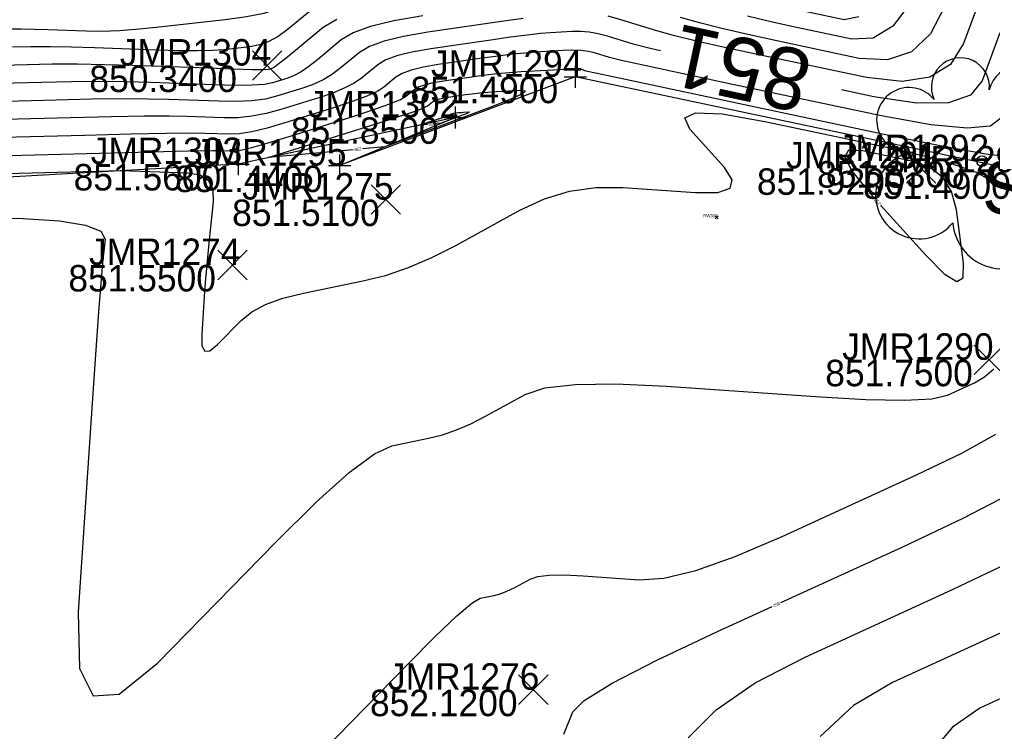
# Model space of a CAD drawing. Extents: x 1654928 to 1810050, y 486881 to 626330.
# Drawn here: x 1801514.13 to 1801558.26, y 489797.37 to 489829.65 of the extents above; entities that cross this region are included whole.
import ezdxf

# ---------------------------------------------------------------- set-up
doc = ezdxf.new("R2010")
doc.units = 0
for name, color, linetype in [('DT_X_Contour_Major', 7, 'Continuous'), ('DT_X_Contour_Minor', 7, 'Continuous'), ('GK_Visualization', 7, 'Continuous'), ('SV_X_Random_Point', 7, 'Continuous'), ('SV_X_Shot_Marker', 7, 'Continuous'), ('SV_X_Text_Elevation', 7, 'Continuous'), ('SV_X_Text_Name', 7, 'Continuous'), ('SV_X_Top_of_Bank', 7, 'Continuous'), ('VG_X_Cells', 7, 'Continuous'), ('VG_X_Text', 7, 'Continuous')]:
    doc.layers.add(name, color=color, linetype=linetype)

msp = doc.modelspace()

# ---------------------------------------------------------------- linework, layer by layer
at = {"layer": 'DT_X_Contour_Major'}
for points in [[(1801526.541, 489830.649), (1801526.157, 489830.333), (1801525.78, 489830.118), (1801525.204, 489829.93), (1801524.429, 489829.769), (1801523.455, 489829.635), (1801520.593, 489829.314), (1801519.572, 489829.211), (1801518.658, 489829.145), (1801517.85, 489829.115), (1801517.148, 489829.12), (1801515.416, 489829.184), (1801514.789, 489829.203), (1801514.203, 489829.213), (1801513.661, 489829.214)], [(1801543.196, 489828.229), (1801542.61, 489828.367), (1801541.961, 489828.539), (1801540.801, 489828.891), (1801540.375, 489829.004), (1801539.964, 489829.078), (1801539.568, 489829.114), (1801539.189, 489829.111), (1801538.198, 489829.051), (1801537.751, 489829.014), (1801537.152, 489828.947), (1801536.401, 489828.849), (1801535.497, 489828.722), (1801532.887, 489828.342), (1801531.995, 489828.188), (1801531.28, 489828.014), (1801530.74, 489827.818), (1801530.375, 489827.6), (1801529.638, 489826.993), (1801529.312, 489826.767), (1801528.89, 489826.547), (1801528.37, 489826.331), (1801527.754, 489826.12), (1801525.98, 489825.565), (1801525.319, 489825.386), (1801524.669, 489825.264), (1801524.029, 489825.2), (1801523.399, 489825.194), (1801521.733, 489825.255), (1801520.934, 489825.269), (1801519.786, 489825.264), (1801518.288, 489825.24), (1801516.442, 489825.197), (1801511.052, 489825.058)], [(1801558.591, 489829.045), (1801557.789, 489826.872), (1801557.256, 489826.216), (1801556.26, 489825.877), (1801554.802, 489825.856), (1801552.88, 489826.152), (1801551.409, 489826.463)], [(1801527.895, 489796.5), (1801531.703, 489800.397), (1801532.982, 489801.682), (1801533.962, 489802.613), (1801534.643, 489803.19), (1801535.026, 489803.415), (1801535.649, 489803.542), (1801535.884, 489803.601), (1801536.125, 489803.682), (1801536.369, 489803.787), (1801536.619, 489803.914), (1801537.29, 489804.283), (1801537.629, 489804.395), (1801538.143, 489804.457), (1801538.832, 489804.467), (1801539.695, 489804.427), (1801542.231, 489804.25), (1801543.349, 489804.323), (1801544.802, 489804.674), (1801546.589, 489805.304), (1801548.71, 489806.213), (1801554.813, 489809.007), (1801556.856, 489809.993), (1801558.409, 489810.856)]]:
    msp.add_lwpolyline(points, dxfattribs=at)
at = {"layer": 'DT_X_Contour_Minor'}
for points in [[(1801558.073, 489831.626), (1801556.942, 489828.567), (1801556.349, 489827.609), (1801555.418, 489827.033), (1801554.15, 489826.837), (1801552.543, 489827.022), (1801547.808, 489828.022), (1801546.178, 489828.373), (1801544.838, 489828.677), (1801543.79, 489828.934), (1801543.032, 489829.144), (1801541.4, 489829.64), (1801540.829, 489829.8)], [(1801527.34, 489830.066), (1801526.264, 489829.18), (1801525.856, 489828.883), (1801525.439, 489828.657), (1801525.011, 489828.501), (1801524.574, 489828.416), (1801523.395, 489828.284), (1801522.875, 489828.245), (1801522.198, 489828.229), (1801521.365, 489828.235), (1801520.375, 489828.263), (1801517.527, 489828.367), (1801516.494, 489828.399), (1801515.532, 489828.416), (1801514.64, 489828.418), (1801513.818, 489828.405)], [(1801556.096, 489830.261), (1801555.442, 489829.003), (1801554.576, 489828.188), (1801553.498, 489827.818), (1801552.206, 489827.891), (1801548.479, 489828.679), (1801547.157, 489828.967), (1801545.987, 489829.241), (1801544.969, 489829.502), (1801544.104, 489829.749)], [(1801554.536, 489830.396), (1801553.735, 489829.344), (1801552.846, 489828.799), (1801551.87, 489828.761), (1801549.15, 489829.335), (1801548.136, 489829.56), (1801547.136, 489829.805)], [(1801536.97, 489829.703), (1801535.877, 489829.547), (1801532.652, 489829.077), (1801531.551, 489828.888), (1801530.667, 489828.672), (1801530, 489828.43), (1801529.549, 489828.162), (1801528.638, 489827.411), (1801528.281, 489827.146), (1801527.894, 489826.916), (1801527.476, 489826.72), (1801527.027, 489826.557), (1801525.791, 489826.17), (1801525.279, 489826.047), (1801524.671, 489825.968), (1801523.967, 489825.933), (1801523.168, 489825.942), (1801520.906, 489826.025), (1801519.95, 489826.047), (1801518.778, 489826.049), (1801517.39, 489826.034), (1801515.786, 489825.999), (1801511.219, 489825.881)], [(1801532.417, 489829.813), (1801531.106, 489829.587), (1801530.054, 489829.33), (1801529.26, 489829.042), (1801528.724, 489828.723), (1801527.639, 489827.829), (1801527.25, 489827.525), (1801526.898, 489827.285), (1801526.581, 489827.108), (1801526.301, 489826.995), (1801525.602, 489826.776), (1801525.239, 489826.709), (1801524.673, 489826.672), (1801523.906, 489826.666), (1801522.936, 489826.69), (1801520.08, 489826.795), (1801518.967, 489826.824), (1801517.771, 489826.835), (1801516.492, 489826.828), (1801515.13, 489826.801), (1801511.386, 489826.705)], [(1801528.52, 489829.655), (1801527.898, 489829.284), (1801526.639, 489828.247), (1801526.219, 489827.905), (1801525.901, 489827.654), (1801525.687, 489827.497), (1801525.575, 489827.432), (1801525.413, 489827.381), (1801525.199, 489827.371), (1801524.676, 489827.376), (1801523.844, 489827.399), (1801522.704, 489827.438), (1801519.253, 489827.564), (1801517.983, 489827.602), (1801516.764, 489827.621), (1801515.594, 489827.622), (1801514.474, 489827.603), (1801511.553, 489827.528)], [(1801552.194, 489829.78), (1801551.533, 489829.63), (1801549.82, 489829.992)], [(1801558.635, 489825.178), (1801558.163, 489824.823), (1801557.102, 489824.722), (1801555.453, 489824.875), (1801553.216, 489825.283), (1801546.466, 489826.709), (1801544.219, 489827.186), (1801542.541, 489827.55), (1801541.431, 489827.799), (1801540.889, 489827.934), (1801540.203, 489828.143), (1801539.92, 489828.208), (1801539.587, 489828.246), (1801539.202, 489828.258), (1801538.767, 489828.244), (1801537.537, 489828.17), (1801537.04, 489828.132), (1801536.471, 489828.074), (1801535.831, 489827.996), (1801535.118, 489827.897), (1801533.121, 489827.606), (1801532.44, 489827.489), (1801531.893, 489827.355), (1801531.48, 489827.205), (1801531.201, 489827.039), (1801530.637, 489826.575), (1801530.343, 489826.388), (1801529.886, 489826.177), (1801529.265, 489825.942), (1801528.48, 489825.683), (1801526.168, 489824.96), (1801525.36, 489824.724), (1801524.667, 489824.56), (1801524.091, 489824.467), (1801523.631, 489824.446), (1801522.56, 489824.485), (1801521.917, 489824.491), (1801520.793, 489824.478), (1801519.186, 489824.446), (1801517.098, 489824.395), (1801510.885, 489824.235)], [(1801510.719, 489823.412), (1801517.754, 489823.593), (1801520.084, 489823.652), (1801521.8, 489823.692), (1801522.901, 489823.713), (1801523.387, 489823.716), (1801523.863, 489823.698), (1801524.153, 489823.734), (1801524.665, 489823.856), (1801525.4, 489824.062), (1801526.357, 489824.354), (1801529.206, 489825.246), (1801530.16, 489825.554), (1801530.882, 489825.808), (1801531.375, 489826.009), (1801531.636, 489826.156), (1801532.027, 489826.478), (1801532.22, 489826.593), (1801532.506, 489826.697), (1801532.885, 489826.789), (1801533.356, 489826.87), (1801534.739, 489827.072), (1801535.261, 489827.142), (1801535.791, 489827.201), (1801536.33, 489827.25), (1801536.876, 489827.289), (1801538.344, 489827.377), (1801538.836, 489827.402), (1801539.21, 489827.414), (1801539.466, 489827.411), (1801539.605, 489827.394), (1801539.818, 489827.329), (1801540.251, 489827.231), (1801541.392, 489826.986), (1801543.24, 489826.593), (1801545.796, 489826.052), (1801553.553, 489824.413), (1801556.105, 489823.895), (1801557.944, 489823.567), (1801559.07, 489823.43)], [(1801532.853, 489825.917), (1801532.96, 489825.981), (1801533.119, 489826.038), (1801533.329, 489826.09), (1801533.591, 489826.135), (1801534.359, 489826.247), (1801534.662, 489826.287), (1801534.996, 489826.322), (1801535.361, 489826.353), (1801535.756, 489826.38), (1801536.85, 489826.445), (1801537.078, 489826.418), (1801536.942, 489826.286), (1801536.441, 489826.05), (1801535.577, 489825.711), (1801530.692, 489823.882), (1801529.683, 489823.788)], [(1801529.265, 489823.749), (1801525.405, 489823.392), (1801530.353, 489824.94), (1801531.29, 489825.239), (1801531.983, 489825.472), (1801532.432, 489825.638), (1801532.636, 489825.738), (1801532.853, 489825.917)], [(1801508.89, 489822.546), (1801518.763, 489822.8), (1801521.769, 489822.707), (1801522.323, 489822.609), (1801522.7, 489822.356), (1801522.898, 489821.946), (1801522.918, 489821.381), (1801522.733, 489819.665), (1801522.667, 489819.022), (1801522.607, 489818.378), (1801522.554, 489817.735), (1801522.507, 489817.091), (1801522.391, 489815.374), (1801522.403, 489814.863), (1801522.527, 489814.615), (1801522.762, 489814.631), (1801523.109, 489814.911), (1801524.182, 489816.009), (1801524.661, 489816.395), (1801525.292, 489816.73), (1801526.075, 489817.013), (1801527.01, 489817.246), (1801529.707, 489817.796), (1801530.729, 489818.052), (1801531.77, 489818.405), (1801532.831, 489818.857), (1801533.912, 489819.408), (1801536.821, 489821.006), (1801537.931, 489821.52), (1801539.078, 489821.862), (1801540.262, 489822.032), (1801541.484, 489822.032), (1801544.792, 489821.801), (1801545.803, 489821.807), (1801546.358, 489821.999), (1801546.455, 489822.376), (1801546.095, 489822.938), (1801544.524, 489824.685), (1801544.296, 489825.197), (1801544.787, 489825.425), (1801545.998, 489825.368), (1801547.93, 489825.027), (1801554.04, 489823.736), (1801556.054, 489823.244), (1801557.514, 489822.737), (1801558.419, 489822.214)], [(1801532.626, 489824.891), (1801532.189, 489824.851), (1801533.366, 489825.22), (1801533.505, 489825.267), (1801533.594, 489825.3), (1801533.635, 489825.32), (1801533.678, 489825.356)], [(1801533.678, 489825.356), (1801533.7, 489825.369), (1801533.732, 489825.38), (1801533.774, 489825.39), (1801533.826, 489825.399), (1801534.04, 489825.43), (1801534.107, 489825.437), (1801534.18, 489825.443), (1801534.259, 489825.448), (1801534.478, 489825.461), (1801534.523, 489825.456), (1801534.496, 489825.43), (1801534.396, 489825.382), (1801534.223, 489825.315), (1801533.246, 489824.949), (1801533.044, 489824.93)], [(1801556.615, 489821.03), (1801556.399, 489821.85), (1801556, 489822.488), (1801555.417, 489822.943), (1801554.65, 489823.215), (1801552.358, 489823.699), (1801551.729, 489823.722), (1801551.561, 489823.425), (1801551.853, 489822.81), (1801552.605, 489821.877), (1801552.897, 489821.552)], [(1801553.177, 489821.24), (1801555.225, 489818.963), (1801556.069, 489818.12), (1801556.637, 489817.779), (1801556.928, 489817.939), (1801556.943, 489818.6), (1801556.615, 489821.03)], [(1801509.186, 489820.781), (1801514.279, 489820.623), (1801515.945, 489820.521), (1801517.122, 489820.332), (1801517.811, 489820.057), (1801518.011, 489819.695), (1801517.895, 489818.614), (1801517.829, 489817.858), (1801517.72, 489816.398), (1801517.568, 489814.234), (1801517.372, 489811.367), (1801516.792, 489802.784), (1801516.853, 489800.225), (1801517.472, 489798.986), (1801518.648, 489799.066), (1801520.382, 489800.465), (1801525.748, 489805.957), (1801527.587, 489807.775), (1801529.078, 489809.11), (1801530.222, 489809.962), (1801531.018, 489810.33), (1801532.678, 489810.669), (1801533.306, 489810.826), (1801533.947, 489811.044), (1801534.6, 489811.322), (1801535.265, 489811.661), (1801537.056, 489812.644), (1801537.96, 489812.945), (1801539.331, 489813.109), (1801541.167, 489813.137), (1801543.47, 489813.028), (1801550.231, 489812.557), (1801552.507, 489812.428), (1801554.264, 489812.396), (1801555.501, 489812.461), (1801556.218, 489812.622), (1801557.439, 489813.181), (1801557.887, 489813.445), (1801558.316, 489813.818)], [(1801548.648, 489803.213), (1801554.153, 489805.734), (1801556.931, 489807.048), (1801558.994, 489808.119), (1801560.34, 489808.945), (1801560.971, 489809.528), (1801561.7, 489810.756), (1801561.952, 489811.183), (1801562.163, 489811.543), (1801562.331, 489811.836), (1801562.459, 489812.062), (1801562.955, 489812.959)], [(1801564.697, 489807.458), (1801563.755, 489805.759), (1801563.59, 489805.467), (1801563.425, 489805.182), (1801562.824, 489804.166), (1801562.445, 489803.816), (1801561.637, 489803.32), (1801560.4, 489802.678), (1801558.733, 489801.889), (1801553.715, 489799.592), (1801551.957, 489798.55), (1801550.444, 489797.149)], [(1801544.46, 489797.085), (1801545.728, 489798.354), (1801547.492, 489799.575), (1801549.753, 489800.748), (1801556.443, 489803.812), (1801558.666, 489804.863), (1801560.316, 489805.719), (1801560.588, 489805.887)], [(1801565.569, 489804.708), (1801564.467, 489802.72), (1801564.304, 489802.429), (1801564.162, 489802.181), (1801564.042, 489801.976), (1801563.75, 489801.484), (1801563.498, 489801.251), (1801562.959, 489800.921), (1801562.134, 489800.493), (1801561.023, 489799.967), (1801557.678, 489798.435), (1801556.439, 489797.57), (1801555.231, 489796.125)], [(1801538.821, 489797.244), (1801539.219, 489798.266), (1801539.742, 489798.781), (1801541.011, 489799.559), (1801543.027, 489800.6), (1801545.79, 489801.905), (1801548.266, 489803.039)]]:
    msp.add_lwpolyline(points, dxfattribs=at)
at = {"layer": 'GK_Visualization'}
for p, q in [((1801545.675, 489820.621), (1801545.809, 489820.754)), ((1801545.675, 489820.754), (1801545.809, 489820.621))]:
    msp.add_line(p, q, dxfattribs=at)
at = {"layer": 'SV_X_Random_Point'}
for p, q in [((1801524.69, 489826.895), (1801526.023, 489828.23)), ((1801524.69, 489828.23), (1801526.023, 489826.895)), ((1801554.349, 489822.236), (1801555.682, 489823.571)), ((1801554.349, 489823.571), (1801555.682, 489822.236)), ((1801530.077, 489820.82), (1801531.41, 489822.155)), ((1801530.077, 489822.155), (1801531.41, 489820.82)), ((1801523.124, 489817.854), (1801524.457, 489819.189)), ((1801523.124, 489819.189), (1801524.457, 489817.854)), ((1801557.429, 489813.557), (1801558.762, 489814.892)), ((1801557.429, 489814.892), (1801558.762, 489813.557)), ((1801536.764, 489798.598), (1801538.098, 489799.933)), ((1801536.764, 489799.933), (1801538.098, 489798.598))]:
    msp.add_line(p, q, dxfattribs=at)
at = {"layer": 'SV_X_Shot_Marker'}
for p, q in [((1801539.336, 489827.557), (1801539.336, 489826.557)), ((1801538.836, 489827.057), (1801539.836, 489827.057)), ((1801539.336, 489827.057), (1801539.336, 489827.057)), ((1801533.885, 489825.715), (1801533.885, 489824.715)), ((1801533.385, 489825.215), (1801534.385, 489825.215)), ((1801533.885, 489825.215), (1801533.885, 489825.215)), ((1801524.048, 489823.6), (1801524.048, 489822.6)), ((1801528.648, 489823.528), (1801528.648, 489822.528)), ((1801523.548, 489823.1), (1801524.548, 489823.1)), ((1801524.048, 489823.1), (1801524.048, 489823.1)), ((1801528.148, 489823.028), (1801529.148, 489823.028)), ((1801528.648, 489823.028), (1801528.648, 489823.028))]:
    msp.add_line(p, q, dxfattribs=at)
at = {"layer": 'SV_X_Top_of_Bank'}
msp.add_lwpolyline([(1801559.863, 489822.721), (1801539.336, 489827.057), (1801528.648, 489823.028), (1801533.885, 489825.215), (1801524.048, 489823.1), (1801504.227, 489821.976), (1801498.255, 489815.137), (1801490.955, 489811.4), (1801479.493, 489812.14), (1801473.308, 489811.885), (1801466.247, 489811.095)], dxfattribs=at)
at = {"layer": 'VG_X_Cells'}
msp.add_circle((1801557.78, 489823.231), 0.24, dxfattribs=at)
for centre, radius, start, end in [((1801556.797, 489826.598), 1.317, 354.0047, 205.9741), ((1801559.607, 489826.06), 1.553, 323.83, 165.0376), ((1801554.471, 489825.095), 1.471, 39.0625, 279.5412), ((1801554.927, 489821.682), 1.974, 96.1722, 320.5737), ((1801558.727, 489820.626), 2.284, 184.9476, 19.4572)]:
    msp.add_arc(centre, radius, start, end, dxfattribs=at)

# ---------------------------------------------------------------- texts
at = {"layer": 'DT_X_Contour_Major'}
msp.add_text('851', height=2.8, rotation=167.8624, dxfattribs=at).set_placement((1801550.193, 489828.141))
at = {"layer": 'DT_X_Contour_Minor'}
for rotation, p in [(5.2941, (1801532.684, 489824.826)), (5.2941, (1801529.322, 489823.684)), (311.9552, (1801552.879, 489821.467)), (204.6032, (1801548.572, 489803.256))]:
    msp.add_text('852', height=0.14, rotation=rotation, dxfattribs=at).set_placement(p)
at = {"layer": 'GK_Visualization'}
msp.add_text('RW302', height=0.14, dxfattribs=at).set_placement((1801545.139, 489820.688))
at = {"layer": 'SV_X_Text_Elevation'}
for s, p in [('850.3400', (1801517.298, 489826.363)), ('851.4900', (1801531.863, 489825.857)), ('851.8500', (1801526.44, 489824.015)), ('851.5600', (1801516.585, 489821.9)), ('851.4400', (1801521.185, 489821.828)), ('851.3300', (1801550.298, 489822.031)), ('851.9200', (1801547.571, 489821.703)), ('851.4900', (1801552.39, 489821.521)), ('851.5100', (1801523.772, 489820.288)), ('851.5500', (1801516.346, 489817.322)), ('851.7500', (1801550.67, 489813.024)), ('852.1200', (1801530.024, 489798.066))]:
    msp.add_text(s, height=1.2, dxfattribs=at).set_placement(p)
at = {"layer": 'SV_X_Text_Name'}
for s, p in [('JMR1304', (1801518.677, 489827.563)), ('JMR1294', (1801532.788, 489827.057)), ('JMR1302', (1801527.205, 489825.215)), ('JMR1303', (1801517.36, 489823.1)), ('JMR1292', (1801551.233, 489823.231)), ('JMR1295', (1801522.092, 489823.028)), ('JMR1291', (1801548.893, 489822.903)), ('JMR1293', (1801553.306, 489822.721)), ('JMR1275', (1801524.225, 489821.488)), ('JMR1274', (1801517.281, 489818.522)), ('JMR1290', (1801551.435, 489814.224)), ('JMR1276', (1801530.837, 489799.266))]:
    msp.add_text(s, height=1.2, dxfattribs=at).set_placement(p)
at = {"layer": 'VG_X_Text'}
msp.add_text('SIZE? 18" KIND? MAPLE', height=2.4, dxfattribs=at).set_placement((1801557.78, 489820.831))

doc.saveas('drawing.dxf')
